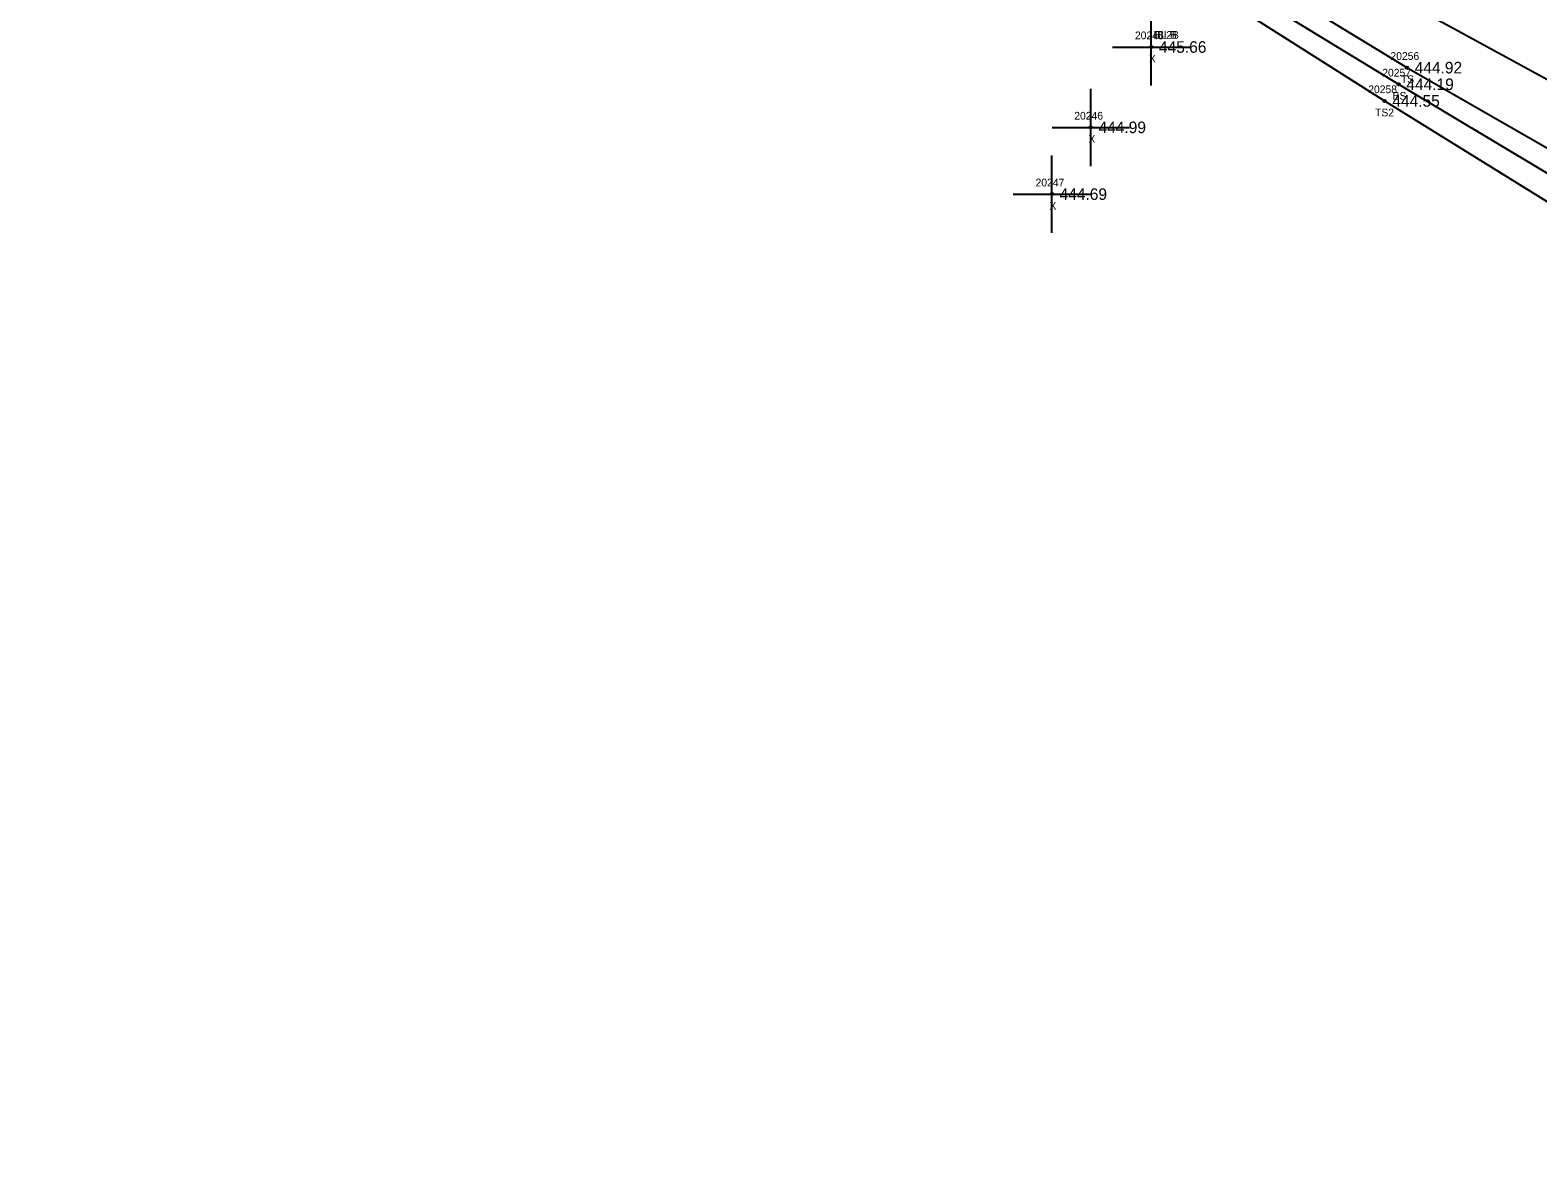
# Model space of a CAD drawing. Extents: x 1810114 to 1811498, y 790790 to 791824.
# Drawn here: x 1810337.9 to 1810533, y 791266.7 to 791412.3 of the extents above; entities that cross this region are included whole.
import ezdxf

# ---------------------------------------------------------------- set-up
doc = ezdxf.new("R2010")
doc.units = 0
for name, color, linetype in [('RD_DTM_BkLn2', 7, 'Continuous'), ('RD_DTM_BkLn_txCode', 7, 'Continuous'), ('RD_EX_Misc', 7, 'Continuous'), ('RD_EX_Misc_txCode', 7, 'Continuous'), ('RD_EX_Road', 7, 'Continuous'), ('RD_EX_TX_Misc_ELEV', 7, 'Continuous'), ('RD_SMD_Locator', 7, 'Continuous')]:
    doc.layers.add(name, color=color, linetype=linetype)

msp = doc.modelspace()

# ---------------------------------------------------------------- linework, layer by layer
at = {"layer": 'RD_DTM_BkLn2'}
for points in [[(1810136.46, 791613.23), (1810225.09, 791566.55), (1810313.34, 791519.56), (1810402.58, 791471.61), (1810490.03, 791423.34), (1810516.06, 791407.46), (1810541.24, 791393.02), (1810575.56, 791368.65), (1810662.82, 791320.73), (1810730.85, 791285.33), (1810742.82, 791282.19), (1810752.34, 791280.87), (1810757.12, 791283.77)], [(1810135.37, 791610.75), (1810224.14, 791564.21), (1810311.68, 791516.56), (1810401.2, 791468.88), (1810488.81, 791421.27), (1810514.98, 791405.31), (1810539.89, 791390.39), (1810572.74, 791363.8), (1810659.47, 791316.31), (1810726.51, 791276.73), (1810738.6, 791270.6), (1810748.52, 791266.73), (1810763.99, 791268.4)], [(1810133.65, 791608.34), (1810222.15, 791560.96), (1810310.01, 791513.91), (1810399.26, 791465.14), (1810487.96, 791419.17), (1810513.17, 791403.16), (1810538.21, 791387.66)]]:
    msp.add_lwpolyline(points, dxfattribs=at)
at = {"layer": 'RD_EX_Misc'}
for p, q in [((1810482.97, 791405.13), (1810482.97, 791415.13)), ((1810477.97, 791410.13), (1810487.97, 791410.13)), ((1810475.15, 791394.74), (1810475.15, 791404.74)), ((1810470.15, 791399.74), (1810480.15, 791399.74)), ((1810470.11, 791386.1), (1810470.11, 791396.1)), ((1810465.11, 791391.1), (1810475.11, 791391.1))]:
    msp.add_line(p, q, dxfattribs=at)
at = {"layer": 'RD_EX_Road'}
msp.add_lwpolyline([(1810138.18, 791616.8), (1810226.92, 791569.59), (1810315.11, 791521.87), (1810404.37, 791475.11), (1810492.73, 791428.56), (1810580.86, 791380.55), (1810670.21, 791334.43), (1810759.54, 791287.61)], dxfattribs=at)
at = {"layer": 'RD_SMD_Locator'}
for centre in [(1810482.97, 791410.13), (1810516.06, 791407.46), (1810514.98, 791405.31), (1810513.17, 791403.16), (1810475.15, 791399.74), (1810470.11, 791391.1)]:
    msp.add_circle(centre, 0.15, dxfattribs=at)

# ---------------------------------------------------------------- texts
at = {"layer": 'RD_DTM_BkLn_txCode'}
for s, p in [('BL2B', (1810483.27, 791411.19)), ('BLB', (1810483.72, 791411.19)), ('20256', (1810513.92, 791408.46)), ('20257', (1810512.86, 791406.31)), ('20258', (1810511.05, 791404.16)), ('TS', (1810515.27, 791405.46)), ('BS', (1810514.2, 791403.31)), ('TS2', (1810511.93, 791401.16))]:
    msp.add_text(s, height=1, dxfattribs=at).set_placement(p)
at = {"layer": 'RD_EX_Misc_txCode'}
for s, p in [('20245', (1810480.86, 791411.13)), ('X', (1810482.66, 791408.13)), ('20246', (1810473.01, 791400.74)), ('X', (1810474.84, 791397.74)), ('20247', (1810468, 791392.1)), ('X', (1810469.8, 791389.1))]:
    msp.add_text(s, height=1, dxfattribs=at).set_placement(p)
at = {"layer": 'RD_EX_TX_Misc_ELEV'}
for s, p in [('445.66', (1810483.97, 791409.38)), ('444.92', (1810517.06, 791406.71)), ('444.19', (1810515.98, 791404.56)), ('444.55', (1810514.17, 791402.41)), ('444.99', (1810476.15, 791398.99)), ('444.69', (1810471.11, 791390.35))]:
    msp.add_text(s, height=1.5, dxfattribs=at).set_placement(p)

doc.saveas('drawing.dxf')
